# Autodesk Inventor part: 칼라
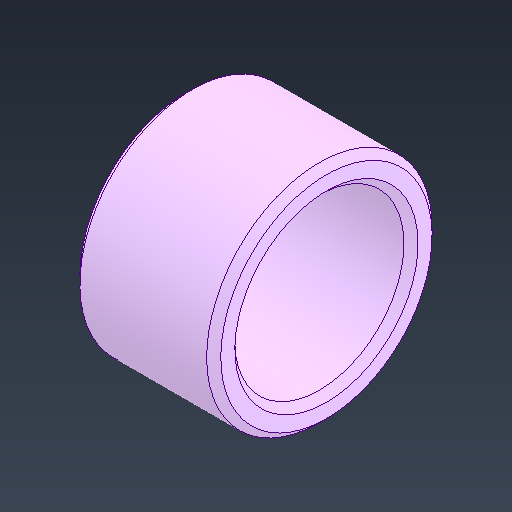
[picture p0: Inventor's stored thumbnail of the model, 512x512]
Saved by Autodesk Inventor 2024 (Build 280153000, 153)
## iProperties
Created: 2024-05
Part Number: 칼라
Material: 강철, 합금
Document SubType Name: Modeling
Designer: kh_501
Density: 7.73 g/cm^3
Appearance: 기본값
Author: jhkim
Sending System: Autodesk Inventor 2025
Preprocessor: ST-DEVELOPER v20
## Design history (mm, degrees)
node "칼라1"
node "솔리드2"
node "솔리드1"
